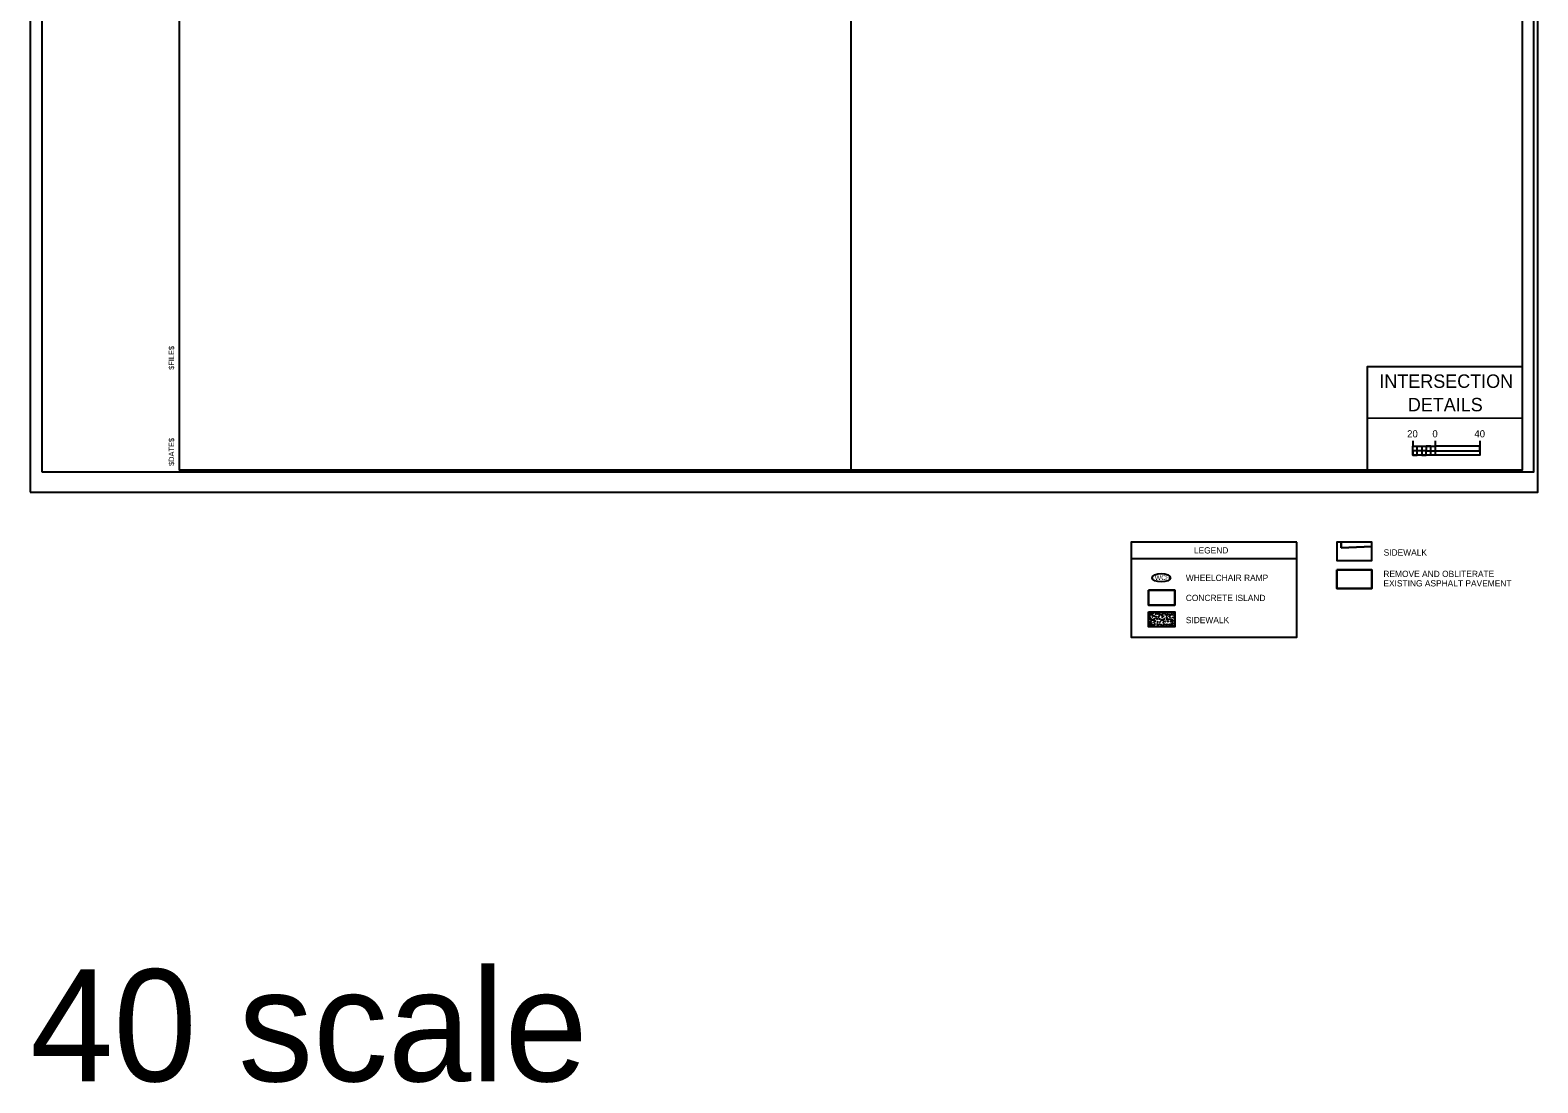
# Model space of a CAD drawing. Extents: x 2431000 to 2534000, y 645879 to 714000.
# Drawn here: x 2462836 to 2464519, y 660614 to 661789 of the extents above; entities that cross this region are included whole.
import ezdxf

# ---------------------------------------------------------------- set-up
doc = ezdxf.new("R2010")
doc.units = 0
for name, color, linetype in [('Default', 7, 'Continuous'), ('Level 25', 7, 'Continuous'), ('Old_Level_1', 7, 'Continuous'), ('Old_Level_40', 7, 'Continuous'), ('Prop DSN Text', 7, 'Continuous'), ('Prop Rem of Exist Asph Pvmt', 7, 'Continuous'), ('Prop Shade Light', 7, 'Continuous'), ('Prop WCC CELL', 7, 'Continuous'), ('Scratch_Level_1', 7, 'Continuous'), ('Sheet Plan CELL', 7, 'Continuous'), ('Sheet Plot Border Inside CELL', 7, 'Continuous'), ('Sheet Plot Border Outside CELL', 7, 'Continuous'), ('Sheet Title CELL', 7, 'Continuous'), ('Sheet Typical CELL', 7, 'Continuous')]:
    doc.layers.add(name, color=color, linetype=linetype)

msp = doc.modelspace()

# ---------------------------------------------------------------- linework, layer by layer
at = {"layer": 'Level 25'}
msp.add_lwpolyline([(2464084.4, 661164.1), (2464084.4, 661147.3), (2464113.6, 661147.3), (2464113.6, 661164.1), (2464084.4, 661164.1)], dxfattribs=at)
for points in [[(2464086.8, 661127.7), (2464086.1, 661128.3), (2464086.3, 661127.3)], [(2464092.7, 661137.6), (2464092, 661138.3), (2464092.1, 661137.2)], [(2464094.5, 661131.8), (2464093.8, 661132.4), (2464094, 661131.3)], [(2464097.4, 661138.5), (2464096.6, 661139.1), (2464096.8, 661138.1)], [(2464101.4, 661127.9), (2464100.7, 661128.5), (2464100.8, 661127.4)], [(2464103.7, 661137.4), (2464102.9, 661138), (2464103.1, 661136.9)], [(2464105.5, 661131.5), (2464104.7, 661132.1), (2464104.9, 661131)], [(2464110.8, 661137.9), (2464110.1, 661138.5), (2464110.2, 661137.5)], [(2464111.2, 661128.4), (2464110.5, 661129), (2464110.7, 661128)], [(2464094.7, 661125.7), (2464093.9, 661126.3), (2464094.1, 661125.3)], [(2464104.8, 661123.9), (2464104, 661124.5), (2464104.2, 661123.5)], [(2464105.6, 661125.5), (2464104.9, 661126.1), (2464105, 661125)]]:
    msp.add_lwpolyline(points, close=True, dxfattribs=at)
for centre, radius in [((2464085.4, 661137.8), 0.131), ((2464085.4, 661135.6), 0.131), ((2464085.5, 661131.5), 0.131), ((2464085.5, 661128.6), 0.131), ((2464085.9, 661133.7), 0.356), ((2464086.6, 661139.1), 0.356), ((2464087.1, 661137), 0.356), ((2464087.2, 661131.9), 0.131), ((2464087.2, 661129.7), 0.131), ((2464088.4, 661127.6), 0.131), ((2464088.9, 661131.1), 0.356), ((2464088.7, 661134.3), 0.131), ((2464088.8, 661136), 0.131), ((2464089.3, 661138.1), 0.356), ((2464090.4, 661135.3), 0.131), ((2464090.6, 661139.5), 0.131), ((2464090.5, 661128.4), 0.131), ((2464090.6, 661130.1), 0.131), ((2464091.1, 661132.2), 0.356), ((2464092.2, 661129.4), 0.131), ((2464092.8, 661134.4), 0.356), ((2464093.5, 661139.3), 0.131), ((2464094.6, 661137.8), 0.356), ((2464094.6, 661128.5), 0.356), ((2464095.3, 661134.2), 0.131), ((2464096.4, 661131.9), 0.356), ((2464096.3, 661137.5), 0.131), ((2464096.3, 661135.3), 0.131), ((2464097.1, 661128.3), 0.131), ((2464098, 661136.7), 0.356), ((2464098.1, 661131.6), 0.131), ((2464098.1, 661129.4), 0.131), ((2464099.8, 661130.8), 0.356), ((2464099.7, 661135.7), 0.131), ((2464099.7, 661134.1), 0.131), ((2464100.3, 661137.8), 0.356), ((2464101.4, 661135), 0.131), ((2464101.5, 661129.8), 0.131), ((2464101.8, 661139.3), 0.131), ((2464102.1, 661131.9), 0.356), ((2464103.2, 661129.1), 0.131), ((2464104.6, 661136), 0.131), ((2464104.6, 661133.7), 0.131), ((2464105.5, 661137.5), 0.356), ((2464106, 661129.2), 0.356), ((2464107.3, 661131.6), 0.356), ((2464107.3, 661137.2), 0.131), ((2464107.3, 661135), 0.131), ((2464108, 661134.2), 0.131), ((2464108.1, 661139.1), 0.131), ((2464108.9, 661136.4), 0.356), ((2464109.1, 661131.3), 0.131), ((2464109.1, 661129.1), 0.131), ((2464109.6, 661132.8), 0.131), ((2464110.8, 661130.5), 0.356), ((2464112, 661133.6), 0.356), ((2464112, 661138.6), 0.356), ((2464111.9, 661136.4), 0.131), ((2464112.3, 661130), 0.131), ((2464085, 661126.4), 0.356), ((2464085.8, 661124.4), 0.131), ((2464087.4, 661125.8), 0.131), ((2464087.4, 661123.7), 0.131), ((2464089, 661125.1), 0.356), ((2464090.8, 661124.1), 0.131), ((2464091.3, 661126.2), 0.356), ((2464092.4, 661123.4), 0.131), ((2464095.1, 661124.2), 0.131), ((2464096.5, 661125.9), 0.356), ((2464098.3, 661125.6), 0.131), ((2464098.3, 661123.4), 0.131), ((2464100, 661124.8), 0.356), ((2464101.7, 661123.8), 0.131), ((2464102.2, 661125.9), 0.356), ((2464107.4, 661123.9), 0.356), ((2464107.5, 661125.6), 0.356), ((2464109.2, 661125.3), 0.131), ((2464109.6, 661126.4), 0.131), ((2464110.9, 661124.5), 0.356), ((2464111.9, 661126.7), 0.356), ((2464112.5, 661124.1), 0.131)]:
    msp.add_circle(centre, radius, dxfattribs=at)
at = {"layer": 'Old_Level_1'}
msp.add_lwpolyline([(2464294.5, 661217.8), (2464294.5, 661197), (2464333.7, 661197), (2464333.7, 661217.8), (2464294.5, 661217.8)], dxfattribs=at)
for points in [[(2464294.5, 661186.7), (2464333.7, 661186.7), (2464333.7, 661166), (2464294.5, 661166)], [(2464084.4, 661164.1), (2464113.6, 661164.1), (2464113.6, 661147.3), (2464084.4, 661147.3)], [(2464084.4, 661139.9), (2464113.6, 661139.9), (2464113.6, 661123.1), (2464084.4, 661123.1)]]:
    msp.add_lwpolyline(points, close=True, dxfattribs=at)
at = {"layer": 'Old_Level_40'}
for p, q in [((2464379.4, 661330.9), (2464379.4, 661324.7)), ((2464404.4, 661330.9), (2464404.4, 661324.7))]:
    msp.add_line(p, q, dxfattribs=at)
msp.add_lwpolyline([(2464454.4, 661330.9), (2464454.4, 661314.7), (2464379.4, 661314.7), (2464379.4, 661324.7), (2464404.4, 661324.7)], dxfattribs=at)
for points in [[(2464384.4, 661319.7), (2464379.4, 661319.7), (2464379.4, 661314.7), (2464384.4, 661314.7)], [(2464389.4, 661319.7), (2464384.4, 661319.7), (2464384.4, 661324.7), (2464389.4, 661324.7)], [(2464394.4, 661319.7), (2464389.4, 661319.7), (2464389.4, 661314.7), (2464394.4, 661314.7)], [(2464399.4, 661324.7), (2464394.4, 661324.7), (2464394.4, 661319.7), (2464399.4, 661319.7)], [(2464404.4, 661314.7), (2464399.4, 661314.7), (2464399.4, 661319.7), (2464404.4, 661319.7)], [(2464454.4, 661324.7), (2464404.4, 661324.7), (2464404.4, 661319.7), (2464454.4, 661319.7)]]:
    msp.add_lwpolyline(points, close=True, dxfattribs=at)
at = {"layer": 'Prop Rem of Exist Asph Pvmt'}
msp.add_lwpolyline([(2464294.5, 661186.7), (2464294.5, 661166), (2464333.7, 661166), (2464333.7, 661186.7), (2464294.5, 661186.7)], dxfattribs=at)
at = {"layer": 'Prop Shade Light'}
for p, q in [((2464299.6, 661211.2), (2464299.3, 661217.8)), ((2464333.7, 661217.8), (2464299.3, 661217.8)), ((2464299.3, 661217.8), (2464299.6, 661211.2)), ((2464333.7, 661212.9), (2464299.6, 661211.2)), ((2464299.6, 661211.2), (2464333.7, 661212.9)), ((2464333.7, 661212.9), (2464333.7, 661217.8))]:
    msp.add_line(p, q, dxfattribs=at)
msp.add_lwpolyline([(2464299.3, 661217.8), (2464294.5, 661217.8), (2464294.5, 661197), (2464333.7, 661197), (2464333.7, 661212.9)], dxfattribs=at)
at = {"layer": 'Prop WCC CELL'}
msp.add_ellipse((2464098.6, 661177.9), major_axis=(10.1, 0), ratio=0.462467, dxfattribs=at)
at = {"layer": 'Sheet Plan CELL'}
msp.add_line((2464065, 661199.5), (2464250, 661199.5), dxfattribs=at)
for points in [[(2464502, 661413.3), (2464328.5, 661413.3), (2464328.5, 661355.8)], [(2464502, 661355.9), (2464328.5, 661355.8), (2464328.5, 661298.4)]]:
    msp.add_lwpolyline(points, dxfattribs=at)
msp.add_lwpolyline([(2464250, 661217.8), (2464065, 661217.8), (2464065, 661111.7), (2464250, 661111.7)], close=True, dxfattribs=at)
at = {"layer": 'Sheet Plot Border Inside CELL'}
msp.add_lwpolyline([(2462848.6, 661296), (2464514.6, 661296), (2464514.6, 662351), (2462848.6, 662351)], close=True, dxfattribs=at)
at = {"layer": 'Sheet Plot Border Outside CELL'}
msp.add_lwpolyline([(2462835.6, 661273.5), (2464519.1, 661273.5), (2464519.1, 662373.5), (2462835.6, 662373.5)], close=True, dxfattribs=at)
at = {"layer": 'Sheet Typical CELL'}
for p, q in [((2463752.1, 662348.5), (2463752.1, 661298.5)), ((2463002.1, 661298.5), (2463002.1, 661298.5)), ((2463002.1, 661298.5), (2463002.1, 661298.5)), ((2463002.1, 661298.5), (2463002.1, 661298.5)), ((2463002.1, 661298.5), (2463002.1, 661298.5)), ((2463002.1, 661298.5), (2463002.1, 661298.5)), ((2463002.1, 661298.5), (2463002.1, 661298.5))]:
    msp.add_line(p, q, dxfattribs=at)
msp.add_lwpolyline([(2464502.1, 662348.5), (2463002.1, 662348.5), (2463002.1, 661298.5), (2464502.1, 661298.5)], close=True, dxfattribs=at)
msp.add_lwpolyline([(2463039.6, 661298.5), (2463039.6, 661298.5)], dxfattribs=at)

# ---------------------------------------------------------------- texts
at = {"layer": 'Default'}
for s, p in [('LEGEND', (2464135, 661205)), ('REMOVE AND OBLITERATE', (2464346.6, 661178.7)), ('EXISTING ASPHALT PAVEMENT', (2464346.6, 661168.2))]:
    msp.add_text(s, height=7, dxfattribs=at).set_placement(p)
for s, rotation, p in [('SIDEWALK', 0.0175, (2464346.9, 661202.6)), ('WHEELCHAIR RAMP', 359.9999, (2464126, 661174.3)), ('CONCRETE ISLAND', 359.9999, (2464126, 661151.9)), ('SIDEWALK', 359.9999, (2464126, 661127.2))]:
    msp.add_text(s, height=7, rotation=rotation, dxfattribs=at).set_placement(p)
at = {"layer": 'Old_Level_40'}
for s, p in [('20', (2464373.1, 661334.6)), ('0', (2464401.3, 661334.6)), ('40', (2464448.2, 661334.6))]:
    msp.add_text(s, height=8, dxfattribs=at).set_placement(p)
at = {"layer": 'Prop DSN Text'}
for s, p in [('INTERSECTION', (2464342.1, 661389.9)), ('DETAILS', (2464373.9, 661363.7))]:
    msp.add_text(s, height=15, rotation=360, dxfattribs=at).set_placement(p)
at = {"layer": 'Prop WCC CELL'}
msp.add_text('WCR', height=5.4, dxfattribs=at).set_placement((2464091.4, 661175.3))
at = {"layer": 'Scratch_Level_1'}
msp.add_text('40 scale', height=125, dxfattribs=at).set_placement((2462835.6, 660615.8))
at = {"layer": 'Sheet Title CELL'}
for s, p in [('$FILE$', (2462996.3, 661410)), ('$DATE$', (2462996.3, 661302.7))]:
    msp.add_text(s, height=6, rotation=90, dxfattribs=at).set_placement(p)

doc.saveas('drawing.dxf')
